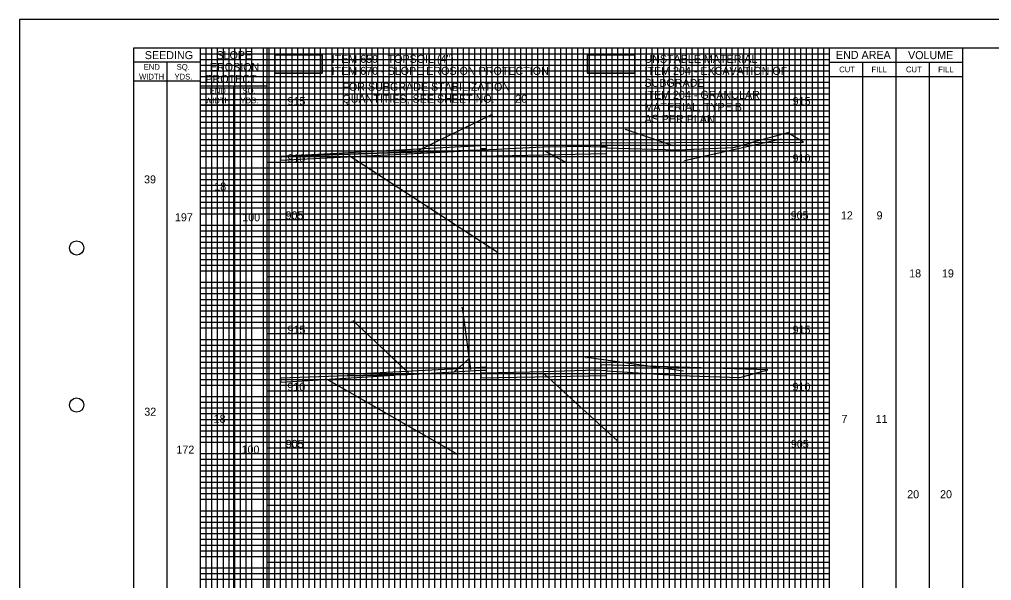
# Model space of a CAD drawing. Extents: x -73 to 160, y -2 to 1877.
# Drawn here: x -10 to 75, y 1093.4 to 1142.5 of the extents above; entities that cross this region are included whole.
import ezdxf

# ---------------------------------------------------------------- set-up
doc = ezdxf.new("R2010")
doc.units = 0
for name, color, linetype in [('DR_P_Flood_Boundary', 7, 'Continuous'), ('GK_Cells', 7, 'Continuous'), ('PV_P_Drive', 7, 'Continuous'), ('PV_P_EOP', 7, 'Continuous'), ('RD_X_Fence', 7, 'Continuous'), ('TX_X_5', 7, 'Continuous'), ('UT_P_Water_Cells', 7, 'Continuous'), ('XS_P_Pavt_Surface', 7, 'Continuous'), ('XS_P_Special_Benching', 7, 'Continuous'), ('XS_X_Ground_Line', 7, 'Continuous')]:
    doc.layers.add(name, color=color, linetype=linetype)

msp = doc.modelspace()

# ---------------------------------------------------------------- linework, layer by layer
at = {"layer": 'DR_P_Flood_Boundary'}
for p, q in [((15.832, 1035), (15.832, 1140)), ((20.832, 1035), (20.832, 1140)), ((25.832, 1035), (25.832, 1140)), ((30.832, 1035), (30.832, 1140)), ((35.832, 1035), (35.832, 1140)), ((40.832, 1035), (40.832, 1140)), ((45.832, 1035), (45.832, 1140)), ((50.832, 1035), (50.832, 1140)), ((55.832, 1035), (55.832, 1140)), ((5.832, 1135), (60.832, 1135)), ((11.665, 1130), (60.832, 1130)), ((11.665, 1125), (60.832, 1125)), ((11.665, 1120), (60.832, 1120)), ((11.665, 1115), (60.832, 1115)), ((11.665, 1110), (60.832, 1110)), ((11.665, 1105), (60.832, 1105)), ((11.665, 1100), (60.832, 1100)), ((11.665, 1095), (60.832, 1095))]:
    msp.add_line(p, q, dxfattribs=at)
at = {"layer": 'GK_Cells'}
msp.add_lwpolyline([(0, 1140), (157.5, 1140), (157.5, 1035), (0, 1035)], close=True, dxfattribs=at)
for centre in [(-5, 1122.5), (-5, 1108.75)]:
    msp.add_circle(centre, 0.625, dxfattribs=at)
at = {"layer": 'PV_P_Drive'}
msp.add_lwpolyline([(12.332, 1139.413), (16.472, 1139.413), (16.472, 1137.797), (12.332, 1137.797)], close=True, dxfattribs=at)
msp.add_lwpolyline([(12.332, 1137.797), (16.472, 1137.797), (16.472, 1139.413), (12.332, 1139.413), (12.332, 1137.797)], dxfattribs=at)
at = {"layer": 'PV_P_EOP'}
msp.add_lwpolyline([(39.681, 1139.413), (43.821, 1139.413), (43.821, 1137.797), (39.681, 1137.797)], close=True, dxfattribs=at)
msp.add_lwpolyline([(39.681, 1137.797), (43.821, 1137.797), (43.821, 1139.413), (39.681, 1139.413), (39.681, 1137.797)], dxfattribs=at)
at = {"layer": 'RD_X_Fence'}
for p, q in [((24.862, 1131.026), (31.301, 1134.179)), ((47.168, 1131.451), (42.99, 1132.853)), ((30.832, 1131.464), (12.832, 1130.512)), ((40.832, 1131.56), (40.83, 1131.414)), ((40.83, 1131.414), (41.332, 1131.424)), ((54.036, 1131.733), (40.832, 1131.664)), ((40.832, 1131.664), (40.832, 1131.56)), ((56.601, 1132.024), (48.138, 1130.133)), ((54.036, 1131.733), (58.57, 1131.756)), ((12.832, 1130.182), (30.332, 1131.063)), ((22.21, 1130.825), (12.832, 1130.512)), ((12.832, 1130.512), (22.21, 1130.825)), ((12.832, 1130.512), (12.832, 1130.182)), ((18.833, 1130.597), (31.773, 1122.163)), ((30.332, 1131.063), (22.21, 1130.825)), ((22.21, 1130.825), (30.332, 1131.063)), ((30.332, 1131.204), (30.832, 1131.214)), ((30.332, 1131.063), (30.332, 1131.204)), ((30.332, 1131.063), (30.332, 1130.537)), ((30.332, 1130.537), (41.332, 1130.757)), ((35.978, 1130.959), (37.647, 1130.056)), ((41.332, 1130.757), (41.332, 1131.305)), ((29.481, 1111.863), (28.731, 1117.289)), ((24.03, 1111.581), (19.177, 1116.119)), ((28.005, 1111.671), (29.253, 1112.761)), ((48.073, 1111.719), (39.602, 1112.912)), ((28.292, 1111.922), (18.721, 1111.41)), ((28.005, 1111.671), (28.292, 1111.922)), ((28.292, 1111.922), (28.005, 1111.671)), ((30.832, 1112.058), (28.292, 1111.922)), ((30.332, 1111.798), (30.832, 1111.808)), ((30.832, 1111.953), (30.832, 1112.058)), ((30.832, 1111.808), (30.832, 1111.953)), ((55.43, 1111.823), (40.832, 1112.258)), ((40.832, 1112.258), (40.832, 1112.153)), ((40.832, 1112.153), (40.832, 1112.008)), ((40.832, 1112.008), (41.332, 1112.018)), ((41.332, 1112.018), (41.332, 1111.739)), ((12.832, 1110.765), (22.835, 1111.355)), ((18.726, 1111.318), (12.832, 1111.095)), ((12.832, 1111.095), (12.832, 1110.765)), ((16.721, 1111.115), (28.249, 1104.49)), ((22.832, 1111.399), (18.726, 1111.318)), ((23.951, 1111.421), (28.005, 1111.66)), ((28.005, 1111.66), (30.332, 1111.798)), ((30.332, 1111.547), (30.332, 1111.131)), ((30.332, 1111.131), (41.332, 1111.351)), ((35.923, 1111.458), (42.282, 1105.618)), ((41.332, 1111.351), (41.332, 1111.739))]:
    msp.add_line(p, q, dxfattribs=at)
for points in [[(58.57, 1131.756), (57.196, 1132.582), (54.036, 1131.733)], [(30.832, 1131.214), (30.832, 1131.36), (30.832, 1131.464)], [(39.082, 1131.379), (37.818, 1131.354), (35.833, 1131.314), (35.727, 1131.312)], [(41.332, 1131.305), (40.829, 1131.321), (39.082, 1131.379)], [(41.332, 1131.262), (47.532, 1131.1), (52.441, 1131.304), (54.036, 1131.733)], [(41.332, 1131.424), (41.332, 1131.305), (41.332, 1131.262)], [(35.727, 1131.312), (31.71, 1131.103), (30.332, 1131.063)], [(41.332, 1111.739), (47.726, 1111.335), (53, 1111.161), (55.43, 1111.823)], [(18.721, 1111.41), (18.726, 1111.318)], [(18.726, 1111.318), (22.834, 1111.399), (23.951, 1111.421)], [(22.835, 1111.355), (22.832, 1111.399)], [(28.005, 1111.66), (28.005, 1111.671)], [(28.005, 1111.671), (28.005, 1111.66)], [(41.332, 1111.739), (40.395, 1111.798), (35.832, 1111.667), (34.623, 1111.632), (30.332, 1111.547)]]:
    msp.add_lwpolyline(points, dxfattribs=at)
at = {"layer": 'TX_X_5'}
msp.add_lwpolyline([(-10, 1032.5), (160, 1032.5), (160, 1142.5), (-10, 1142.5)], close=True, dxfattribs=at)
at = {"layer": 'UT_P_Water_Cells'}
for p, q in [((6.332, 1035), (6.332, 1140)), ((6.832, 1035), (6.832, 1140)), ((7.332, 1035), (7.332, 1140)), ((7.832, 1035), (7.832, 1140)), ((8.332, 1035), (8.332, 1140)), ((8.832, 1035), (8.832, 1140)), ((9.332, 1035), (9.332, 1140)), ((9.832, 1035), (9.832, 1140)), ((10.332, 1035), (10.332, 1140)), ((11.332, 1035), (11.332, 1140)), ((11.832, 1035), (11.832, 1140)), ((12.332, 1035), (12.332, 1140)), ((12.832, 1035), (12.832, 1140)), ((13.332, 1035), (13.332, 1140)), ((13.832, 1035), (13.832, 1140)), ((14.332, 1035), (14.332, 1140)), ((14.832, 1035), (14.832, 1140)), ((15.332, 1035), (15.332, 1140)), ((16.332, 1035), (16.332, 1140)), ((16.832, 1035), (16.832, 1140)), ((17.332, 1035), (17.332, 1140)), ((17.832, 1035), (17.832, 1140)), ((18.332, 1035), (18.332, 1140)), ((18.832, 1035), (18.832, 1140)), ((19.332, 1035), (19.332, 1140)), ((19.832, 1035), (19.832, 1140)), ((20.332, 1035), (20.332, 1140)), ((21.332, 1035), (21.332, 1140)), ((21.832, 1035), (21.832, 1140)), ((22.332, 1035), (22.332, 1140)), ((22.832, 1035), (22.832, 1140)), ((23.332, 1035), (23.332, 1140)), ((23.832, 1035), (23.832, 1140)), ((24.332, 1035), (24.332, 1140)), ((24.832, 1035), (24.832, 1140)), ((25.332, 1035), (25.332, 1140)), ((26.332, 1035), (26.332, 1140)), ((26.832, 1035), (26.832, 1140)), ((27.332, 1035), (27.332, 1140)), ((27.832, 1035), (27.832, 1140)), ((28.332, 1035), (28.332, 1140)), ((28.832, 1035), (28.832, 1140)), ((29.332, 1035), (29.332, 1140)), ((29.832, 1035), (29.832, 1140)), ((30.332, 1035), (30.332, 1140)), ((31.332, 1035), (31.332, 1140)), ((31.832, 1035), (31.832, 1140)), ((32.332, 1035), (32.332, 1140)), ((32.832, 1035), (32.832, 1140)), ((33.332, 1035), (33.332, 1140)), ((33.832, 1035), (33.832, 1140)), ((34.332, 1035), (34.332, 1140)), ((34.832, 1035), (34.832, 1140)), ((35.332, 1035), (35.332, 1140)), ((36.332, 1035), (36.332, 1140)), ((36.832, 1035), (36.832, 1140)), ((37.332, 1035), (37.332, 1140)), ((37.832, 1035), (37.832, 1140)), ((38.332, 1035), (38.332, 1140)), ((38.832, 1035), (38.832, 1140)), ((39.332, 1035), (39.332, 1140)), ((39.832, 1035), (39.832, 1140)), ((40.332, 1035), (40.332, 1140)), ((41.332, 1035), (41.332, 1140)), ((41.832, 1035), (41.832, 1140)), ((42.332, 1035), (42.332, 1140)), ((42.832, 1035), (42.832, 1140)), ((43.332, 1035), (43.332, 1140)), ((43.832, 1035), (43.832, 1140)), ((44.332, 1035), (44.332, 1140)), ((44.832, 1035), (44.832, 1140)), ((45.332, 1035), (45.332, 1140)), ((46.332, 1035), (46.332, 1140)), ((46.832, 1035), (46.832, 1140)), ((47.332, 1035), (47.332, 1140)), ((47.832, 1035), (47.832, 1140)), ((48.332, 1035), (48.332, 1140)), ((48.832, 1035), (48.832, 1140)), ((49.332, 1035), (49.332, 1140)), ((49.832, 1035), (49.832, 1140)), ((50.332, 1035), (50.332, 1140)), ((51.332, 1035), (51.332, 1140)), ((51.832, 1035), (51.832, 1140)), ((52.332, 1035), (52.332, 1140)), ((52.832, 1035), (52.832, 1140)), ((53.332, 1035), (53.332, 1140)), ((53.832, 1035), (53.832, 1140)), ((54.332, 1035), (54.332, 1140)), ((54.832, 1035), (54.832, 1140)), ((55.332, 1035), (55.332, 1140)), ((56.332, 1035), (56.332, 1140)), ((56.832, 1035), (56.832, 1140)), ((57.332, 1035), (57.332, 1140)), ((57.832, 1035), (57.832, 1140)), ((58.332, 1035), (58.332, 1140)), ((58.832, 1035), (58.832, 1140)), ((59.332, 1035), (59.332, 1140)), ((59.832, 1035), (59.832, 1140)), ((60.332, 1035), (60.332, 1140)), ((5.832, 1139.5), (60.832, 1139.5)), ((5.832, 1139), (60.832, 1139)), ((5.832, 1138.5), (60.832, 1138.5)), ((5.832, 1138), (60.832, 1138)), ((5.832, 1137.5), (60.832, 1137.5)), ((5.832, 1137), (60.832, 1137)), ((5.832, 1136.5), (60.832, 1136.5)), ((5.832, 1136), (60.832, 1136)), ((5.832, 1135.5), (60.832, 1135.5)), ((5.832, 1134.5), (60.832, 1134.5)), ((5.832, 1134), (60.832, 1134)), ((5.832, 1133.5), (60.832, 1133.5)), ((5.832, 1133), (60.832, 1133)), ((5.832, 1132.5), (60.832, 1132.5)), ((5.832, 1132), (60.832, 1132)), ((5.832, 1131.5), (60.832, 1131.5)), ((5.832, 1131), (60.832, 1131)), ((5.832, 1130.5), (60.832, 1130.5)), ((5.832, 1129.5), (60.832, 1129.5)), ((5.832, 1129), (60.832, 1129)), ((5.832, 1128.5), (60.832, 1128.5)), ((5.832, 1128), (60.832, 1128)), ((5.832, 1127.5), (60.832, 1127.5)), ((5.832, 1127), (60.832, 1127)), ((5.832, 1126.5), (60.832, 1126.5)), ((5.832, 1126), (60.832, 1126)), ((5.832, 1125.5), (60.832, 1125.5)), ((5.832, 1124.5), (60.832, 1124.5)), ((5.832, 1124), (60.832, 1124)), ((5.832, 1123.5), (60.832, 1123.5)), ((5.832, 1123), (60.832, 1123)), ((5.832, 1122.5), (60.832, 1122.5)), ((5.832, 1122), (60.832, 1122)), ((5.832, 1121.5), (60.832, 1121.5)), ((5.832, 1121), (60.832, 1121)), ((5.832, 1120.5), (60.832, 1120.5)), ((5.832, 1119.5), (60.832, 1119.5)), ((5.832, 1119), (60.832, 1119)), ((5.832, 1118.5), (60.832, 1118.5)), ((5.832, 1118), (60.832, 1118)), ((5.832, 1117.5), (60.832, 1117.5)), ((5.832, 1117), (60.832, 1117)), ((5.832, 1116.5), (60.832, 1116.5)), ((5.832, 1116), (60.832, 1116)), ((5.832, 1115.5), (60.832, 1115.5)), ((5.832, 1114.5), (60.832, 1114.5)), ((5.832, 1114), (60.832, 1114)), ((5.832, 1113.5), (60.832, 1113.5)), ((5.832, 1113), (60.832, 1113)), ((5.832, 1112.5), (60.832, 1112.5)), ((5.832, 1112), (60.832, 1112)), ((5.832, 1111.5), (60.832, 1111.5)), ((5.832, 1111), (60.832, 1111)), ((5.832, 1110.5), (60.832, 1110.5)), ((5.832, 1109.5), (60.832, 1109.5)), ((5.832, 1109), (60.832, 1109)), ((5.832, 1108.5), (60.832, 1108.5)), ((5.832, 1108), (60.832, 1108)), ((5.832, 1107.5), (60.832, 1107.5)), ((5.832, 1107), (60.832, 1107)), ((5.832, 1106.5), (60.832, 1106.5)), ((5.832, 1106), (60.832, 1106)), ((5.832, 1105.5), (60.832, 1105.5)), ((5.832, 1104.5), (60.832, 1104.5)), ((5.832, 1104), (60.832, 1104)), ((5.832, 1103.5), (60.832, 1103.5)), ((5.832, 1103), (60.832, 1103)), ((5.832, 1102.5), (60.832, 1102.5)), ((5.832, 1102), (60.832, 1102)), ((5.832, 1101.5), (60.832, 1101.5)), ((5.832, 1101), (60.832, 1101)), ((5.832, 1100.5), (60.832, 1100.5)), ((5.832, 1099.5), (60.832, 1099.5)), ((5.832, 1099), (60.832, 1099)), ((5.832, 1098.5), (60.832, 1098.5)), ((5.832, 1098), (60.832, 1098)), ((5.832, 1097.5), (60.832, 1097.5)), ((5.832, 1097), (60.832, 1097)), ((5.832, 1096.5), (60.832, 1096.5)), ((5.832, 1096), (60.832, 1096)), ((5.832, 1095.5), (60.832, 1095.5)), ((5.832, 1094.5), (60.832, 1094.5)), ((5.832, 1094), (60.832, 1094)), ((5.832, 1093.5), (60.832, 1093.5))]:
    msp.add_line(p, q, dxfattribs=at)
at = {"layer": 'XS_X_Ground_Line'}
for p, q in [((5.832, 1035), (5.832, 1140)), ((5.832, 1035), (5.832, 1140)), ((11.665, 1035), (11.665, 1140)), ((60.832, 1035), (60.832, 1140)), ((66.667, 1035), (66.667, 1140)), ((72.5, 1035), (72.5, 1140)), ((5.832, 1138.75), (0, 1138.75)), ((2.916, 1035), (2.916, 1138.75)), ((60.832, 1138.75), (72.5, 1138.75)), ((63.75, 1035), (63.75, 1138.75)), ((69.583, 1035), (69.583, 1138.75)), ((60.832, 1137.5), (72.5, 1137.5)), ((5.832, 1137.083), (0, 1137.083)), ((11.665, 1136.667), (5.832, 1136.667)), ((8.749, 1035), (8.749, 1136.667)), ((11.665, 1135), (5.832, 1135))]:
    msp.add_line(p, q, dxfattribs=at)

# ---------------------------------------------------------------- texts
at = {"layer": 'RD_X_Fence'}
for s, p in [('3.2', (31.141, 1134.109)), ('6.1', (42.869, 1132.783)), ('6.8', (37.499, 1129.986)), ('1.9', (48.019, 1130.063)), ('3.1', (31.637, 1122.093)), ('0.6', (28.564, 1117.219)), ('2.0', (19.017, 1116.049)), ('1.9', (29.134, 1112.691)), ('8.7', (39.456, 1112.842)), ('4.7', (42.119, 1105.548)), ('2.1', (28.115, 1104.42))]:
    msp.add_text(s, height=0.14, dxfattribs=at).set_placement(p)
at = {"layer": 'XS_P_Pavt_Surface'}
for s, p in [('915', (13.441, 1135)), ('915', (57.609, 1135)), ('910', (13.43, 1130)), ('910', (57.598, 1130)), ('39', (0.896, 1128.15)), ('18', (7.038, 1127.531)), ('197', (3.597, 1124.834)), ('100', (9.48, 1124.834)), ('905', (13.27, 1125)), ('905', (57.438, 1125)), ('12', (61.829, 1125)), ('9', (64.948, 1125)), ('18', (67.798, 1119.92)), ('19', (70.662, 1119.92)), ('915', (13.441, 1115)), ('915', (57.609, 1115)), ('910', (13.43, 1110)), ('910', (57.598, 1110)), ('32', (0.918, 1107.818)), ('18', (6.98, 1107.198)), ('7', (61.878, 1107.183)), ('11', (64.868, 1107.183)), ('172', (3.724, 1104.501)), ('100', (9.422, 1104.501)), ('905', (13.287, 1105)), ('905', (57.454, 1105)), ('20', (67.627, 1100.596)), ('20', (70.499, 1100.596))]:
    msp.add_text(s, height=0.7, dxfattribs=at).set_placement(p)
at = {"layer": 'XS_P_Special_Benching'}
for s, p in [('ITEM 659 - TOPSOIL (4")', (17.3, 1138.699)), ('UNSTABLE MATERIAL', (44.649, 1138.699)), ('ITEM 670 - SLOPE EROSION PROTECTION', (17.3, 1137.649)), ('ITEM 204 - EXCAVATION OF', (44.649, 1137.649)), ('SUBGRADE', (44.649, 1136.599)), ('FOR SUBGRADE STABILIZATION', (18.237, 1136.257)), ('QUANTITIES, SEE SHEET NO.', (18.237, 1135.207)), ('20', (33.355, 1135.207)), ('ITEM 204 - GRANULAR', (44.649, 1135.549)), ('MATERIAL, TYPE B,', (44.649, 1134.499)), ('AS PER PLAN', (44.649, 1133.449))]:
    msp.add_text(s, height=0.7, dxfattribs=at).set_placement(p)
at = {"layer": 'XS_X_Ground_Line'}
for s, height, p in [('SEEDING', 0.7, (0.964, 1139.025)), ('SLOPE', 0.7, (7.228, 1139.025)), ('END AREA', 0.7, (61.394, 1139.047)), ('VOLUME', 0.7, (67.698, 1139.025)), ('END', 0.5, (0.87, 1138.092)), ('SQ.', 0.5, (3.748, 1138.092)), ('EROSION', 0.7, (6.649, 1137.983)), ('CUT', 0.5, (61.683, 1137.875)), ('FILL', 0.5, (64.502, 1137.875)), ('CUT', 0.5, (67.517, 1137.875)), ('FILL', 0.5, (70.335, 1137.875)), ('WIDTH', 0.5, (0.462, 1137.242)), ('YDS.', 0.5, (3.563, 1137.242)), ('PROTECT.', 0.7, (6.26, 1136.942)), ('END', 0.5, (6.631, 1136.008)), ('SQ.', 0.5, (9.51, 1136.008)), ('WIDTH', 0.5, (6.224, 1135.158)), ('YDS.', 0.5, (9.325, 1135.158))]:
    msp.add_text(s, height=height, dxfattribs=at).set_placement(p)

doc.saveas('drawing.dxf')
